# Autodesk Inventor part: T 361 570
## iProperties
Company: Mayer & Müller AG Schaltgeräte
Created: 2005-12
Part Number: T 361 570
Material: 1.4301
Document SubType Name: Sheet Metal
Designer: I.Baliuc
Manufacturer: Standard
Standards Organization: Custom
Description: Kontaktträgerseitenteil
Density: 7.86 g/cm^3
Sheet Metal Rule: Standard
Abmessung: St.Bl. 3 mm
Author: T.Messerschmitt
Revision Number: 361570
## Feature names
1. Bohrung_12D10 [Hole]
2. Bohrung_12E9 [Hole]
3. Bohrung_10D10 [Hole]
4. Bohrung_8 [Hole]
5. Bohrung_6D10 [Hole]
6. Bohrung_8D10 [Hole]
7. Grobblech1
